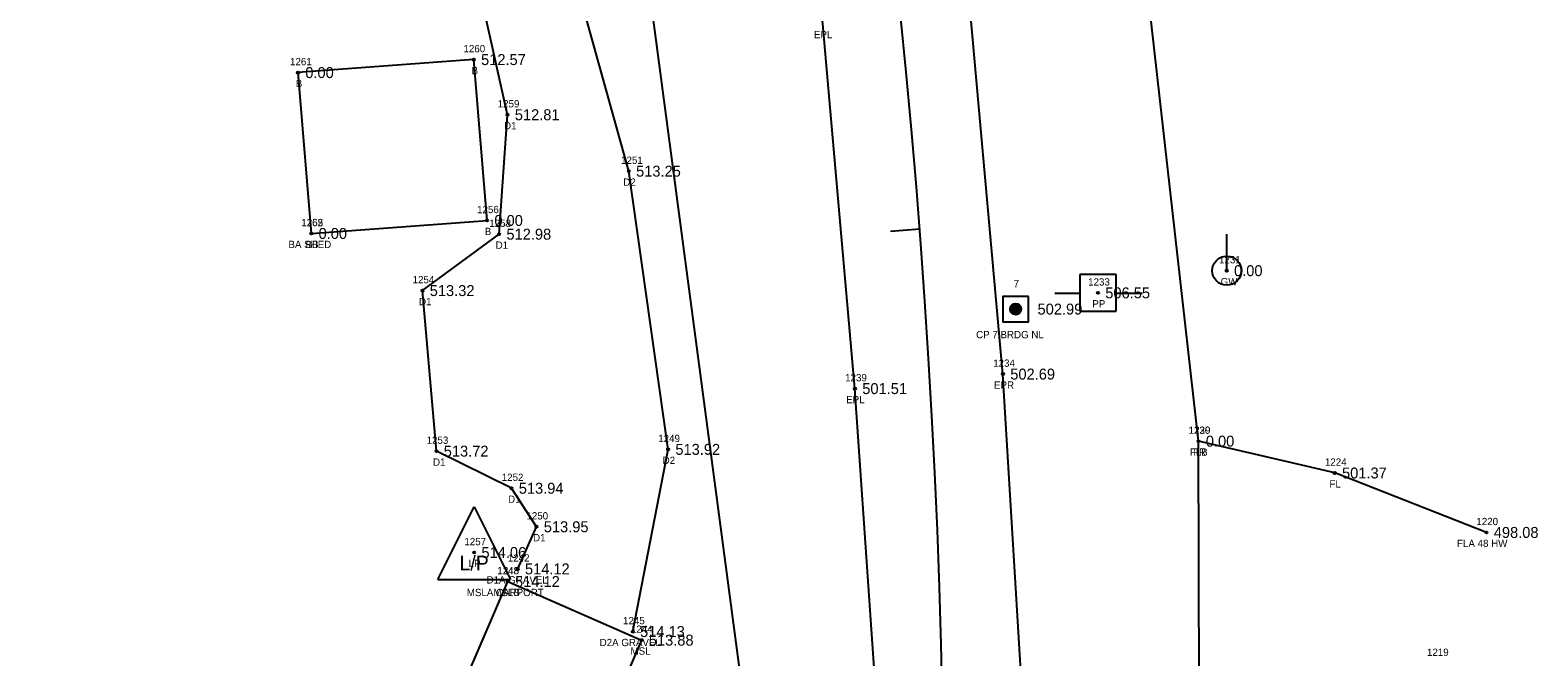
# Model space of a CAD drawing. Extents: x 1649047 to 1650429, y 896228 to 898747.
# Drawn here: x 1649819 to 1650025.8, y 897821 to 897906.9 of the extents above; entities that cross this region are included whole.
import ezdxf

# ---------------------------------------------------------------- set-up
doc = ezdxf.new("R2010")
doc.units = 0
for name, color, linetype in [('RD_EX_Bldg', 7, 'Continuous'), ('RD_EX_Bldg_txCode', 7, 'Continuous'), ('RD_EX_Driveway', 7, 'Continuous'), ('RD_EX_Driveway_txCode', 7, 'Continuous'), ('RD_EX_Fence_Other', 7, 'Continuous'), ('RD_EX_Fence_Other_txCode', 7, 'Continuous'), ('RD_EX_Misc', 7, 'Continuous'), ('RD_EX_Misc_txCode', 7, 'Continuous'), ('RD_EX_Road', 7, 'Continuous'), ('RD_EX_Road_txCode', 7, 'Continuous'), ('RD_EX_TX_Bldg_ELEV', 7, 'Continuous'), ('RD_EX_TX_Driveway_ELEV', 7, 'Continuous'), ('RD_EX_TX_Fence_Other_ELEV', 7, 'Continuous'), ('RD_EX_TX_Misc_ELEV', 7, 'Continuous'), ('RD_EX_TX_Road_ELEV', 7, 'Continuous'), ('RD_EX_TX_UT_ELEV', 7, 'Continuous'), ('RD_EX_UT', 7, 'Continuous'), ('RD_EX_UT_txCode', 7, 'Continuous'), ('RD_EX_VEG', 7, 'Continuous'), ('RD_HC_Cl', 7, 'Continuous'), ('RD_HC_Data_Tic', 7, 'Continuous'), ('RD_HC_Survey', 7, 'Continuous'), ('RD_HC_Survey_ELEV', 7, 'Continuous'), ('RD_HC_Survey_txCode', 7, 'Continuous'), ('RD_SMD_Locator', 7, 'Continuous')]:
    doc.layers.add(name, color=color, linetype=linetype)

msp = doc.modelspace()

# ---------------------------------------------------------------- linework, layer by layer
at = {"layer": 'RD_EX_Bldg'}
msp.add_lwpolyline([(1649857.59, 897879.03), (1649881.7, 897880.81), (1649879.88, 897902.87), (1649855.77, 897901.09), (1649857.59, 897879.03)], dxfattribs=at)
at = {"layer": 'RD_EX_Driveway'}
for points in [[(1649885.9, 897833.04), (1649888.48, 897838.82), (1649885.05, 897844.1), (1649874.76, 897849.19), (1649872.84, 897871.2), (1649883.36, 897878.93), (1649884.51, 897895.31), (1649872.67, 897948.43), (1649859.84, 897995.31), (1649850.73, 898044.7), (1649859.54, 898073.3), (1649873.95, 898086.75), (1649886.51, 898091.37), (1649892.17, 898093.03), (1649896.48, 898096.53)], [(1649901.69, 897824.45), (1649906.53, 897849.43), (1649901.14, 897887.57), (1649884.06, 897948.98), (1649869.85, 897997.68), (1649863.43, 898047.51), (1649871.07, 898067.5), (1649879.87, 898075.97), (1649892.85, 898081.07), (1649899.68, 898079.2)]]:
    msp.add_lwpolyline(points, dxfattribs=at)
at = {"layer": 'RD_EX_Fence_Other'}
for points in [[(1650024.05, 897805.66), (1649992.96, 897767.31), (1649987.75, 897777.51), (1649985.36, 897778.87), (1649980.02, 897794.2), (1649979.42, 897799.4), (1649979.28, 897850.56), (1649966.51, 897963.69), (1649940.2, 898118.22), (1649931.13, 898165.01)], [(1650018.77, 897838.04), (1649997.96, 897846.19), (1649979.28, 897850.56)]]:
    msp.add_lwpolyline(points, dxfattribs=at)
at = {"layer": 'RD_EX_Misc'}
msp.add_lwpolyline([(1649884.54, 897831.31), (1649902.89, 897823.28), (1649895.45, 897805.96), (1649877.11, 897813.99), (1649884.54, 897831.31)], dxfattribs=at)
at = {"layer": 'RD_EX_Road'}
for points in [[(1649905.13, 897459.2), (1649918.81, 897511.88), (1649930.39, 897563.05), (1649939.7, 897612.37), (1649946.83, 897662.25), (1649952.14, 897712.87), (1649954.77, 897762.63), (1649955.64, 897791.88), (1649955.33, 897812.31), (1649952.46, 897859.75), (1649947.95, 897909.71), (1649941.78, 897959.51), (1649933.15, 898009.23), (1649924.03, 898060.85), (1649913.91, 898112.48), (1649904.76, 898159.93)], [(1649885.84, 897465.29), (1649899.42, 897516.76), (1649910.69, 897567.43), (1649919.68, 897616.11), (1649926.54, 897664.67), (1649931.97, 897714.33), (1649935.04, 897763.32), (1649935.22, 897813.54), (1649932.16, 897857.76), (1649927.73, 897907.79), (1649922.24, 897954.81), (1649913.41, 898005.06), (1649903.99, 898056.19), (1649899.68, 898079.2), (1649896.48, 898096.53), (1649894.5, 898108.47), (1649884.77, 898155.82)]]:
    msp.add_lwpolyline(points, dxfattribs=at)
at = {"layer": 'RD_EX_UT'}
for p, q in [((1649983.15, 897873.93), (1649983.15, 897878.93)), ((1649967.98, 897873.4), (1649962.98, 897873.4)), ((1649962.98, 897873.4), (1649962.98, 897868.4)), ((1649967.98, 897868.4), (1649967.98, 897873.4)), ((1649959.55, 897870.83), (1649963.02, 897870.83)), ((1649967.91, 897870.83), (1649971.55, 897870.83)), ((1649962.98, 897868.4), (1649967.98, 897868.4)), ((1649874.93, 897831.57), (1649879.93, 897841.57)), ((1649879.93, 897841.57), (1649884.93, 897831.57)), ((1649874.93, 897831.57), (1649884.93, 897831.57))]:
    msp.add_line(p, q, dxfattribs=at)
msp.add_circle((1649983.15, 897873.93), 2, dxfattribs=at)
at = {"layer": 'RD_EX_VEG'}
msp.add_lwpolyline([(1649617.18, 897070.52), (1649712.19, 897191.88), (1649745.96, 897241.38), (1649814.66, 897340.98), (1649833.89, 897382.46), (1649865.2, 897454.4), (1649884.45, 897522.02), (1649904.5, 897665.19), (1649923.9, 897762.32), (1649882.75, 898072.18)], dxfattribs=at)
at = {"layer": 'RD_HC_Cl'}
msp.add_arc((1648799.37, 897792.37), 1145, 320.82481, 10.99954, dxfattribs=at)
at = {"layer": 'RD_HC_Data_Tic'}
msp.add_line((1649941.04, 897879.61), (1649937.05, 897879.31), dxfattribs=at)
at = {"layer": 'RD_HC_Survey'}
for p, q in [((1649953.45, 897868.48), (1649953.45, 897868.84)), ((1649953.48, 897868.4), (1649953.48, 897868.92)), ((1649953.5, 897868.33), (1649953.5, 897868.98)), ((1649953.53, 897868.29), (1649953.53, 897869.03)), ((1649953.55, 897868.24), (1649953.55, 897869.07)), ((1649953.58, 897868.21), (1649953.58, 897869.11)), ((1649953.6, 897868.17), (1649953.6, 897869.14)), ((1649953.63, 897868.15), (1649953.63, 897869.17)), ((1649953.65, 897868.12), (1649953.65, 897869.19)), ((1649953.68, 897868.09), (1649953.68, 897869.22)), ((1649953.7, 897868.07), (1649953.7, 897869.24)), ((1649953.72, 897868.05), (1649953.72, 897869.26)), ((1649953.75, 897868.03), (1649953.75, 897869.28)), ((1649953.77, 897868.02), (1649953.77, 897869.3)), ((1649953.8, 897868), (1649953.8, 897869.31)), ((1649953.82, 897867.99), (1649953.82, 897869.33)), ((1649953.85, 897867.97), (1649953.85, 897869.34)), ((1649953.87, 897867.96), (1649953.87, 897869.35)), ((1649953.9, 897867.95), (1649953.9, 897869.36)), ((1649953.92, 897867.94), (1649953.92, 897869.37)), ((1649953.95, 897867.93), (1649953.95, 897869.38)), ((1649953.97, 897867.92), (1649953.97, 897869.39)), ((1649954, 897867.91), (1649954, 897869.4)), ((1649954.02, 897867.91), (1649954.02, 897869.41)), ((1649954.05, 897867.9), (1649954.05, 897869.41)), ((1649954.07, 897867.9), (1649954.07, 897869.42)), ((1649954.1, 897867.89), (1649954.1, 897869.42)), ((1649954.12, 897867.89), (1649954.12, 897869.42)), ((1649954.15, 897867.89), (1649954.15, 897869.42)), ((1649954.17, 897867.89), (1649954.17, 897869.43)), ((1649954.2, 897867.89), (1649954.2, 897869.43)), ((1649954.22, 897867.89), (1649954.22, 897869.43)), ((1649954.24, 897867.89), (1649954.24, 897869.43)), ((1649954.27, 897867.89), (1649954.27, 897869.42)), ((1649954.29, 897867.89), (1649954.29, 897869.42)), ((1649954.32, 897867.9), (1649954.32, 897869.42)), ((1649954.34, 897867.9), (1649954.34, 897869.41)), ((1649954.37, 897867.91), (1649954.37, 897869.41)), ((1649954.39, 897867.91), (1649954.39, 897869.4)), ((1649954.42, 897867.92), (1649954.42, 897869.4)), ((1649954.44, 897867.93), (1649954.44, 897869.39)), ((1649954.47, 897867.93), (1649954.47, 897869.38)), ((1649954.49, 897867.94), (1649954.49, 897869.37)), ((1649954.52, 897867.96), (1649954.52, 897869.36)), ((1649954.54, 897867.97), (1649954.54, 897869.35)), ((1649954.57, 897867.98), (1649954.57, 897869.33)), ((1649954.59, 897867.99), (1649954.59, 897869.32)), ((1649954.62, 897868.01), (1649954.62, 897869.3)), ((1649954.64, 897868.03), (1649954.64, 897869.29)), ((1649954.67, 897868.04), (1649954.67, 897869.27)), ((1649954.69, 897868.06), (1649954.69, 897869.25)), ((1649954.71, 897868.08), (1649954.71, 897869.23)), ((1649954.74, 897868.11), (1649954.74, 897869.21)), ((1649954.76, 897868.13), (1649954.76, 897869.18)), ((1649954.79, 897868.16), (1649954.79, 897869.15)), ((1649954.81, 897868.19), (1649954.81, 897869.12)), ((1649954.84, 897868.23), (1649954.84, 897869.09)), ((1649954.86, 897868.27), (1649954.86, 897869.05)), ((1649954.89, 897868.31), (1649954.89, 897869)), ((1649954.91, 897868.36), (1649954.91, 897868.95)), ((1649954.94, 897868.43), (1649954.94, 897868.88)), ((1649954.96, 897868.55), (1649954.96, 897868.77))]:
    msp.add_line(p, q, dxfattribs=at)
msp.add_lwpolyline([(1649955.95, 897870.41), (1649952.45, 897870.41), (1649952.45, 897866.91), (1649955.95, 897866.91)], close=True, dxfattribs=at)
msp.add_circle((1649954.2, 897868.66), 0.769, dxfattribs=at)
at = {"layer": 'RD_SMD_Locator'}
for centre in [(1649879.88, 897902.87), (1649855.77, 897901.09), (1649884.51, 897895.31), (1649901.14, 897887.57), (1649857.59, 897879.03), (1649857.59, 897879.03), (1649881.7, 897880.81), (1649883.36, 897878.93), (1649983.15, 897873.93), (1649872.84, 897871.2), (1649965.49, 897870.89), (1649954.2, 897868.66), (1649952.46, 897859.75), (1649932.16, 897857.76), (1649979.28, 897850.56), (1649979.28, 897850.56), (1649874.76, 897849.19), (1649906.53, 897849.43), (1649997.96, 897846.19), (1649885.05, 897844.1), (1649888.48, 897838.82), (1650018.77, 897838.04), (1649879.93, 897835.29), (1649885.9, 897833.04), (1649884.54, 897831.31), (1649884.54, 897831.31), (1649901.69, 897824.45), (1649902.89, 897823.28)]:
    msp.add_circle(centre, 0.15, dxfattribs=at)

# ---------------------------------------------------------------- texts
at = {"layer": 'RD_EX_Bldg_txCode'}
for s, p in [('1260', (1649878.47, 897903.87)), ('1261', (1649854.68, 897902.09)), ('B', (1649879.57, 897900.87)), ('B', (1649855.46, 897899.09)), ('1256', (1649880.33, 897881.81)), ('1262', (1649856.22, 897880.03)), ('1255', (1649856.24, 897880.03)), ('B', (1649881.39, 897878.81)), ('BA SHED', (1649854.46, 897877.03)), ('BB', (1649856.81, 897877.03))]:
    msp.add_text(s, height=1, dxfattribs=at).set_placement(p)
at = {"layer": 'RD_EX_Driveway_txCode'}
for s, p in [('1259', (1649883.16, 897896.31)), ('D1', (1649884.03, 897893.31)), ('1251', (1649900.08, 897888.57)), ('D2', (1649900.38, 897885.57)), ('1258', (1649882.01, 897879.93)), ('D1', (1649882.88, 897876.93)), ('1254', (1649871.49, 897872.2)), ('D1', (1649872.37, 897869.2)), ('1253', (1649873.41, 897850.19)), ('1249', (1649905.18, 897850.43)), ('D1', (1649874.29, 897847.19)), ('D2', (1649905.78, 897847.43)), ('1252', (1649883.71, 897845.1)), ('D1', (1649884.58, 897842.1)), ('1250', (1649887.1, 897839.82)), ('D1', (1649888.01, 897836.82)), ('1242', (1649884.55, 897834.04)), ('D1A GRAVEL', (1649881.63, 897831.04)), ('1245', (1649900.35, 897825.45)), ('D2A GRAVEL', (1649897.14, 897822.45)), ('1219', (1650010.61, 897821.11))]:
    msp.add_text(s, height=1, dxfattribs=at).set_placement(p)
at = {"layer": 'RD_EX_Fence_Other_txCode'}
for s, p in [('1230', (1649977.9, 897851.56)), ('1229', (1649977.94, 897851.56)), ('FLB', (1649978.08, 897848.56)), ('FR', (1649978.53, 897848.56)), ('1224', (1649996.61, 897847.19)), ('FL', (1649997.23, 897844.19)), ('1220', (1650017.38, 897839.04)), ('FLA 48 HW', (1650014.73, 897836.04))]:
    msp.add_text(s, height=1, dxfattribs=at).set_placement(p)
at = {"layer": 'RD_EX_Misc_txCode'}
for s, p in [('1248', (1649883.1, 897832.31)), ('1243', (1649883.12, 897832.31)), ('MSLA CARPORT', (1649878.92, 897829.31)), ('MSLB', (1649882.57, 897829.31)), ('1244', (1649901.43, 897824.28)), ('MSL', (1649901.38, 897821.28))]:
    msp.add_text(s, height=1, dxfattribs=at).set_placement(p)
at = {"layer": 'RD_EX_Road_txCode'}
for s, p in [('EPL', (1649926.53, 897905.79)), ('1234', (1649951.12, 897860.75)), ('1239', (1649930.81, 897858.76)), ('EPR', (1649951.23, 897857.75)), ('EPL', (1649930.95, 897855.76))]:
    msp.add_text(s, height=1, dxfattribs=at).set_placement(p)
at = {"layer": 'RD_EX_TX_Bldg_ELEV'}
for s, p in [('0.00', (1649856.77, 897900.34)), ('512.57', (1649880.88, 897902.12)), ('0.00', (1649882.7, 897880.06)), ('0.00', (1649858.59, 897878.28)), ('0.00', (1649858.59, 897878.28))]:
    msp.add_text(s, height=1.5, dxfattribs=at).set_placement(p)
at = {"layer": 'RD_EX_TX_Driveway_ELEV'}
for s, p in [('512.81', (1649885.51, 897894.56)), ('513.25', (1649902.14, 897886.82)), ('512.98', (1649884.36, 897878.18)), ('513.32', (1649873.84, 897870.45)), ('513.92', (1649907.53, 897848.68)), ('513.72', (1649875.76, 897848.44)), ('513.94', (1649886.05, 897843.35)), ('513.95', (1649889.48, 897838.07)), ('514.12', (1649886.9, 897832.29)), ('514.13', (1649902.69, 897823.7))]:
    msp.add_text(s, height=1.5, dxfattribs=at).set_placement(p)
at = {"layer": 'RD_EX_TX_Fence_Other_ELEV'}
for s, p in [('0.00', (1649980.28, 897849.81)), ('0.00', (1649980.28, 897849.81)), ('501.37', (1649998.96, 897845.44)), ('498.08', (1650019.77, 897837.29))]:
    msp.add_text(s, height=1.5, dxfattribs=at).set_placement(p)
at = {"layer": 'RD_EX_TX_Misc_ELEV'}
for s, p in [('514.12', (1649885.54, 897830.56)), ('514.12', (1649885.54, 897830.56)), ('513.88', (1649903.89, 897822.53))]:
    msp.add_text(s, height=1.5, dxfattribs=at).set_placement(p)
at = {"layer": 'RD_EX_TX_Road_ELEV'}
for s, p in [('502.69', (1649953.46, 897859)), ('501.51', (1649933.16, 897857.01))]:
    msp.add_text(s, height=1.5, dxfattribs=at).set_placement(p)
at = {"layer": 'RD_EX_TX_UT_ELEV'}
for s, p in [('0.00', (1649984.15, 897873.18)), ('514.06', (1649880.93, 897834.54))]:
    msp.add_text(s, height=1.5, dxfattribs=at).set_placement(p)
at = {"layer": 'RD_EX_UT'}
msp.add_text('L/P', height=2, dxfattribs=at).set_placement((1649877.92, 897832.85))
at = {"layer": 'RD_EX_UT_txCode'}
for s, p in [('1231', (1649982.09, 897874.93)), ('1233', (1649964.14, 897871.89)), ('GW', (1649982.31, 897871.93)), ('PP', (1649964.71, 897868.89)), ('1257', (1649878.59, 897836.29)), ('LP', (1649879.18, 897833.29))]:
    msp.add_text(s, height=1, dxfattribs=at).set_placement(p)
at = {"layer": 'RD_HC_Survey_ELEV'}
for s, p in [('506.55', (1649966.49, 897870.14)), ('502.99', (1649957.2, 897867.91))]:
    msp.add_text(s, height=1.5, dxfattribs=at).set_placement(p)
at = {"layer": 'RD_HC_Survey_txCode'}
for s, p in [('7', (1649953.92, 897871.66)), ('CP 7 BRDG NL', (1649948.77, 897864.66))]:
    msp.add_text(s, height=1, dxfattribs=at).set_placement(p)

doc.saveas('drawing.dxf')
